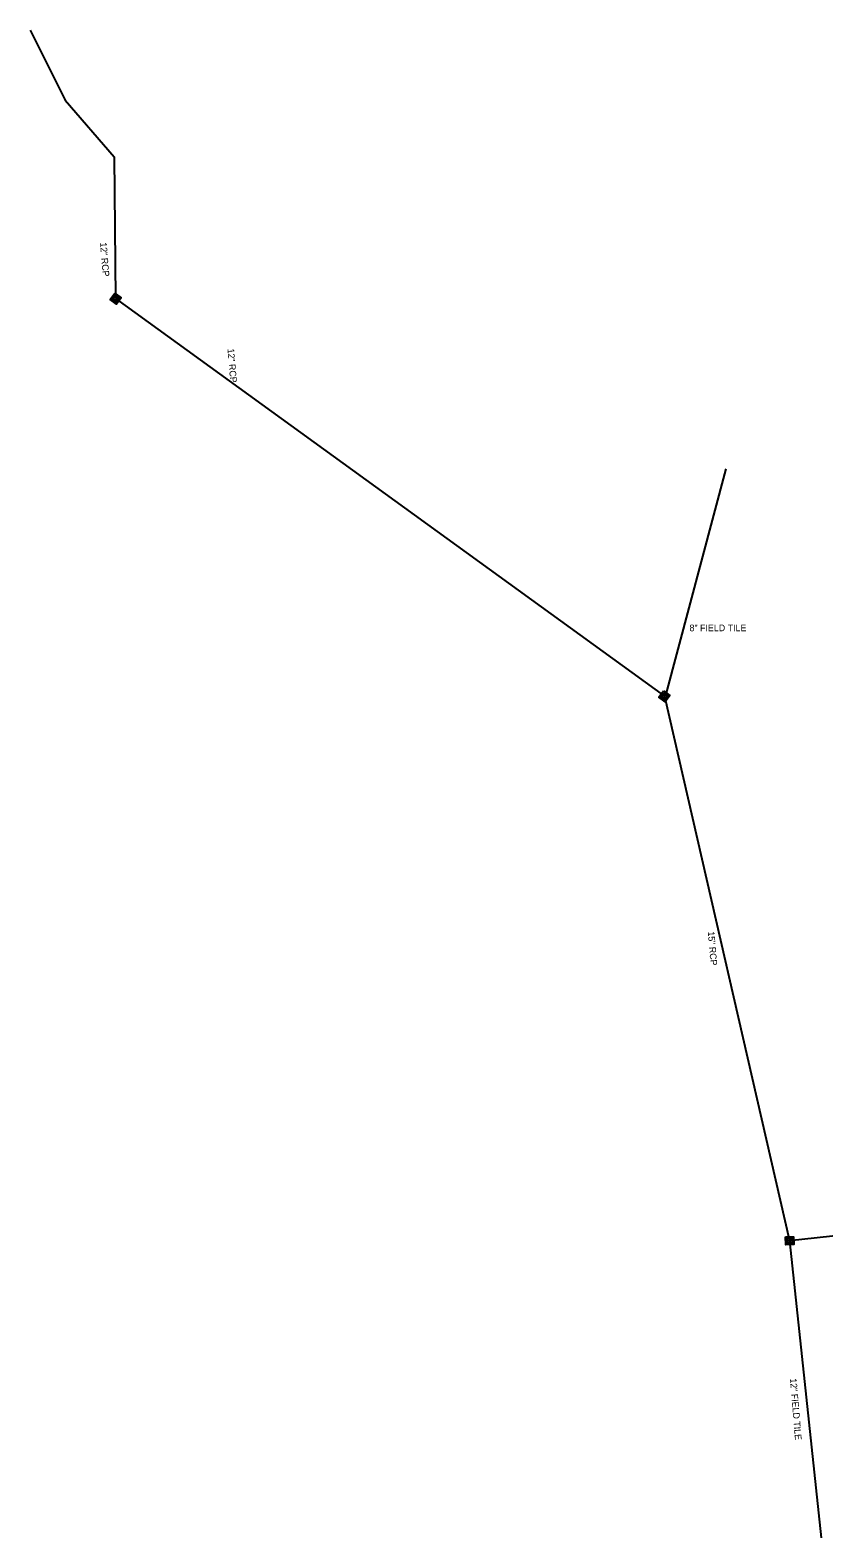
# Model space of a CAD drawing. Extents: x 1600691 to 1601880, y 286054 to 287103.
# Drawn here: x 1600691 to 1601027, y 286466 to 287103 of the extents above; entities that cross this region are included whole.
import ezdxf

# ---------------------------------------------------------------- set-up
doc = ezdxf.new("R2010")
doc.units = 0
for name, color, linetype in [('_CIVIL_CONSTRUCTION', 7, 'Continuous'), ('PV_P_EOP', 7, 'Continuous'), ('SC_Scratch1', 7, 'Continuous'), ('SC_Scratch2', 7, 'Continuous'), ('SH_Text', 7, 'Continuous')]:
    doc.layers.add(name, color=color, linetype=linetype)

msp = doc.modelspace()

# ---------------------------------------------------------------- linework, layer by layer
at = {"layer": '_CIVIL_CONSTRUCTION'}
for p, q in [((1600985.21, 286917.43), (1600959.62, 286821.71)), ((1601012.1, 286591.52), (1601025.35, 286466.11))]:
    msp.add_line(p, q, dxfattribs=at)
for points in [[(1600691.34, 287102.61), (1600706.14, 287072.99), (1600726.86, 287049.17), (1600727.4, 286989.31)], [(1601184.52, 286689.93), (1601114.48, 286602.57), (1601012.1, 286591.52)]]:
    msp.add_lwpolyline(points, dxfattribs=at)
at = {"layer": 'PV_P_EOP'}
for p, q in [((1600726.6, 286989.9), (1600726.6, 286989.9)), ((1600727.4, 286989.31), (1600727.4, 286989.31)), ((1600727.4, 286989.31), (1600727.4, 286989.31)), ((1600727.4, 286989.31), (1600727.4, 286989.31)), ((1600727.99, 286990.11), (1600727.99, 286990.11)), ((1600728.2, 286988.71), (1600728.2, 286988.71)), ((1600728.39, 286990.64), (1600728.39, 286990.64)), ((1600726.4, 286987.97), (1600726.4, 286987.97)), ((1600726.8, 286988.5), (1600726.8, 286988.5)), ((1600958.18, 286820.07), (1600958.18, 286820.07)), ((1600958.38, 286822), (1600958.38, 286822)), ((1600958.58, 286820.6), (1600958.58, 286820.6)), ((1600959.18, 286821.4), (1600959.18, 286821.4)), ((1600959.18, 286821.4), (1600959.18, 286821.4)), ((1600959.18, 286821.4), (1600959.18, 286821.4)), ((1600959.77, 286822.21), (1600959.77, 286822.21)), ((1600959.98, 286820.81), (1600959.98, 286820.81)), ((1600960.17, 286822.74), (1600960.17, 286822.74)), ((1601011.1, 286591.49), (1601011.1, 286591.49)), ((1601012.05, 286593.18), (1601012.05, 286593.18)), ((1601012.07, 286592.51), (1601012.07, 286592.51)), ((1601012.1, 286591.52), (1601012.1, 286591.52)), ((1601012.1, 286591.52), (1601012.1, 286591.52)), ((1601012.1, 286591.52), (1601012.1, 286591.52)), ((1601012.13, 286590.52), (1601012.13, 286590.52)), ((1601012.14, 286589.85), (1601012.14, 286589.85)), ((1601013.1, 286591.54), (1601013.1, 286591.54))]:
    msp.add_line(p, q, dxfattribs=at)
at = {"layer": 'SC_Scratch1'}
for p, q in [((1600726.11, 286989.5), (1600728.57, 286989.86)), ((1600726.27, 286988.71), (1600728.64, 286989.06)), ((1600726.79, 286990.41), (1600727.67, 286990.53)), ((1600727.18, 286988.04), (1600727.97, 286988.15)), ((1600957.89, 286821.6), (1600960.35, 286821.96)), ((1600958.05, 286820.81), (1600960.42, 286821.16)), ((1600958.57, 286822.5), (1600959.45, 286822.63)), ((1600958.96, 286820.14), (1600959.75, 286820.25)), ((1601010.94, 286592), (1601011.55, 286592.65)), ((1601010.97, 286590.87), (1601012.68, 286592.68)), ((1601011.58, 286590.36), (1601013.23, 286592.09)), ((1601012.71, 286590.39), (1601013.26, 286590.96))]:
    msp.add_line(p, q, dxfattribs=at)
for points in [[(1600727.06, 286991.64), (1600729.73, 286989.65), (1600727.74, 286986.97), (1600725.07, 286988.96)], [(1600727.16, 286990.91), (1600729, 286989.54), (1600727.63, 286987.7), (1600725.79, 286989.07)], [(1600727.19, 286990.7), (1600728.8, 286989.51), (1600727.6, 286987.91), (1600726, 286989.1)], [(1600958.83, 286823.74), (1600961.51, 286821.75), (1600959.52, 286819.07), (1600956.85, 286821.06)], [(1600958.94, 286823.01), (1600960.78, 286821.64), (1600959.41, 286819.8), (1600957.57, 286821.17)], [(1600958.97, 286822.8), (1600960.58, 286821.61), (1600959.38, 286820.01), (1600957.78, 286821.2)], [(1601010.39, 286593.14), (1601013.72, 286593.23), (1601013.81, 286589.89), (1601010.48, 286589.8)], [(1601010.92, 286592.63), (1601013.21, 286592.69), (1601013.27, 286590.4), (1601010.98, 286590.34)], [(1601011.07, 286592.49), (1601013.07, 286592.54), (1601013.12, 286590.54), (1601011.13, 286590.49)]]:
    msp.add_lwpolyline(points, close=True, dxfattribs=at)
at = {"layer": 'SH_Text'}
for p, q in [((1600727.4, 286989.31), (1600959.18, 286821.4)), ((1600959.18, 286821.4), (1601012.1, 286591.52))]:
    msp.add_line(p, q, dxfattribs=at)

# ---------------------------------------------------------------- texts
at = {"layer": 'SC_Scratch2'}
for s, p in [('12" RCP', (1600720.85, 287012.88)), ('12" RCP', (1600774.68, 286968.07)), ('15" RCP', (1600977.54, 286722.03)), ('12" FIELD TILE', (1601012.24, 286533.31))]:
    msp.add_text(s, height=2.8, rotation=274.73471, dxfattribs=at).set_placement(p)
msp.add_text('8" FIELD TILE', height=2.8, dxfattribs=at).set_placement((1600969.81, 286848.86))

doc.saveas('drawing.dxf')
